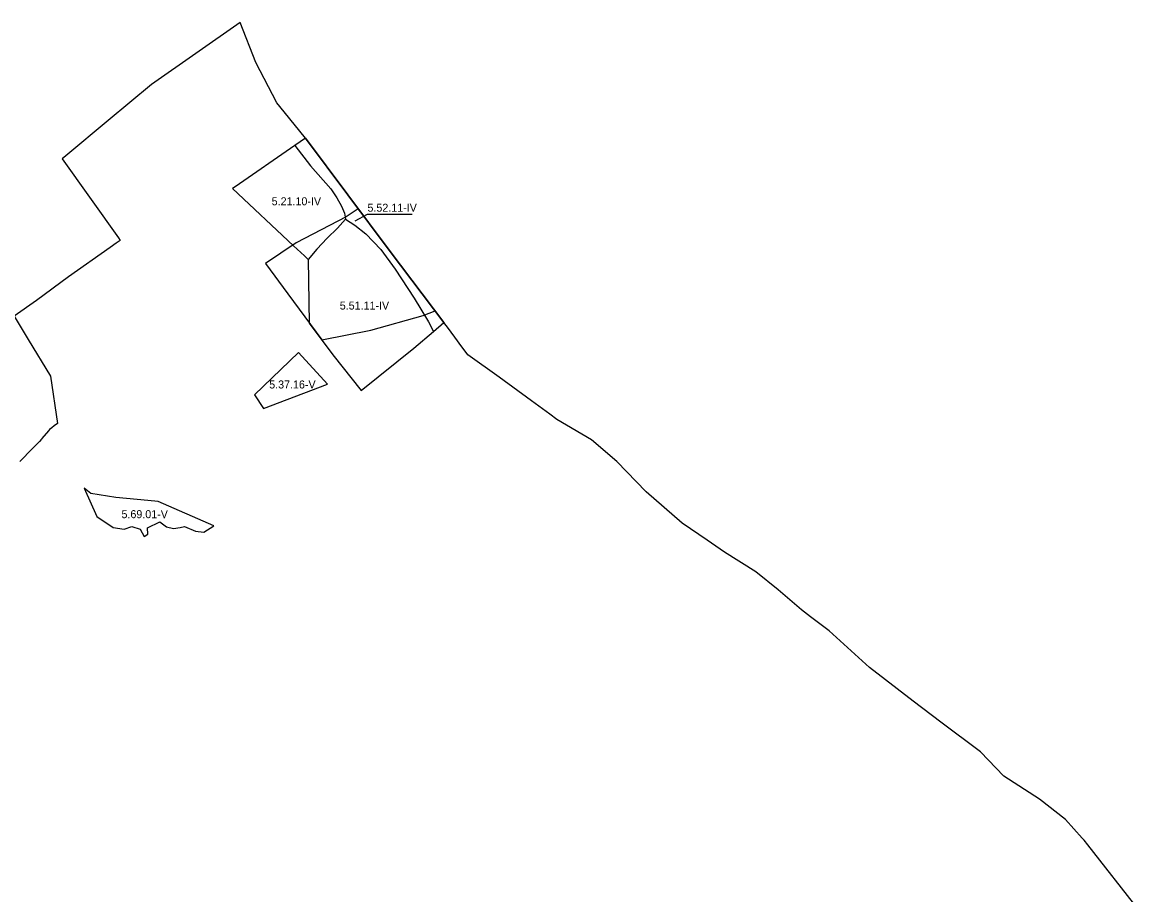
# Model space of a CAD drawing. Extents: x -555156 to -540209, y -1046851 to -1035695.
# Drawn here: x -543396 to -542000, y -1036785 to -1035695 of the extents above; entities that cross this region are included whole.
import ezdxf

# ---------------------------------------------------------------- set-up
doc = ezdxf.new("R2010")
doc.units = 0
for name, color, linetype in [('Vrstva 27', 7, 'Continuous'), ('Vrstva 28', 7, 'Continuous'), ('Vrstva 29', 7, 'Continuous')]:
    doc.layers.add(name, color=color, linetype=linetype)

msp = doc.modelspace()

# ---------------------------------------------------------------- linework, layer by layer
at = {"layer": 'Vrstva 27'}
msp.add_lwpolyline([(-542980.74, -1035942.52), (-542964.97, -1035934.43), (-542909.14, -1035934.43)], dxfattribs=at)
at = {"layer": 'Vrstva 28'}
for points in [[(-542936.69, -1035980.71), (-543042.64, -1035839.41), (-543069.25, -1035806.38), (-543078.47, -1035794.93), (-543104.67, -1035744.61), (-543124.3, -1035694.54), (-543234.87, -1035772.4), (-543289.16, -1035817.01), (-543341.94, -1035861.47), (-543346.51, -1035865.17), (-543276.38, -1035963.9), (-543274.21, -1035966.98), (-543279.27, -1035970.33), (-543286.85, -1035975.71), (-543338.82, -1036012.58), (-543378.67, -1036042.29), (-543406.66, -1036061.87), (-543389.24, -1036090.92), (-543361.26, -1036136.78), (-543352.67, -1036195.74), (-543356.78, -1036198.98), (-543359.45, -1036201.08), (-543362.4, -1036203.41), (-543363.78, -1036205.03), (-543372.06, -1036214.73), (-543372.5, -1036215.25), (-543374.91, -1036218.16), (-543375.33, -1036218.59), (-543383.53, -1036226.94), (-543399.68, -1036243.41)], [(-543056.03, -1035848.65), (-543130.42, -1035899.99), (-543133.72, -1035902.27), (-543057.58, -1035973.76), (-543043.99, -1035986.52), (-543039.28, -1035990.94)], [(-543042.64, -1035839.41), (-543056.03, -1035848.65)], [(-543056.03, -1035848.65), (-543036.31, -1035873.81), (-543011.09, -1035902.59), (-543003.25, -1035913.97), (-542997.68, -1035924.1), (-542993.89, -1035933.2), (-542992.63, -1035940.54)], [(-543042.64, -1035839.41), (-542936.69, -1035980.71), (-542869.66, -1036069.79)], [(-542992.63, -1035940.54), (-543002.49, -1035951.67), (-543015.39, -1035964.32), (-543028.53, -1035977.99), (-543039.28, -1035990.94)], [(-542992.63, -1035940.54), (-542981.06, -1035947.96), (-542967.15, -1035958.84), (-542948.44, -1035978.32), (-542930.48, -1036003.11), (-542906.97, -1036039.04), (-542888.76, -1036068.9), (-542882.84, -1036081.03)], [(-542000.32, -1036804.67), (-542065.05, -1036722.45), (-542069.84, -1036716.38), (-542072.11, -1036713.85), (-542092.81, -1036690.69), (-542125.62, -1036665.28), (-542169.9, -1036636.7), (-542199.3, -1036605.98), (-542248.78, -1036568.89), (-542283.5, -1036542.65), (-542337.95, -1036500.86), (-542388.29, -1036454.98), (-542411.43, -1036437.34), (-542422.75, -1036428.73), (-542451.96, -1036403.63), (-542480.03, -1036381.28), (-542519.01, -1036356.5), (-542540.89, -1036341.56), (-542571.93, -1036320.38), (-542617.03, -1036281.33), (-542653.65, -1036243.36), (-542685.07, -1036216.26), (-542728.49, -1036190.78), (-542737.26, -1036184.38), (-542760.08, -1036167.71), (-542800.8, -1036137.97), (-542839.61, -1036109.9), (-542850.49, -1036095.36), (-542852.5, -1036092.68), (-542864.03, -1036077.27), (-542869.66, -1036069.79), (-542936.69, -1035980.71)], [(-543039.28, -1035990.94), (-543037.82, -1036070.56)], [(-543037.82, -1036070.56), (-543008.45, -1036110.22), (-542973.1, -1036154.53), (-542907.11, -1036101.72), (-542882.84, -1036081.03)], [(-542882.84, -1036081.03), (-542869.66, -1036069.79)], [(-543015.14, -1036146.73), (-543051.27, -1036106.94), (-543106.33, -1036159.96)], [(-543106.33, -1036159.96), (-543094.92, -1036177.31), (-543015.14, -1036146.73)], [(-543226.53, -1036293.22), (-543239.72, -1036292.11), (-543279.75, -1036288.26), (-543310.74, -1036283.2), (-543319.36, -1036276.61), (-543303.31, -1036312.03), (-543282.87, -1036325.85)], [(-543282.87, -1036325.85), (-543269.18, -1036327.76), (-543259.8, -1036324.61), (-543249.14, -1036328.04), (-543244.31, -1036337.19), (-543239.76, -1036334.16), (-543239.82, -1036326.13), (-543224.67, -1036318.72), (-543216.36, -1036324.95), (-543207.38, -1036327.26), (-543199.07, -1036325.91), (-543193.86, -1036324.67), (-543180.16, -1036330.34), (-543169.44, -1036331.52), (-543157.26, -1036323.6), (-543226.53, -1036293.22)]]:
    msp.add_lwpolyline(points, dxfattribs=at)
at = {"layer": 'Vrstva 29'}
msp.add_lwpolyline([(-542976.613526, -1035927.466071), (-542991.700989, -1035937.507996), (-543054.310974, -1035970.11499), (-543092.395996, -1035995.908997), (-543064.487, -1036033.662903), (-543022.072998, -1036091.120972), (-542960.935974, -1036079.307007), (-542895.523987, -1036061.054993), (-542880.644288, -1036055.192351), (-542936.69, -1035980.71), (-542969.60783, -1035936.809204), (-542976.613526, -1035927.466071)], dxfattribs=at)

# ---------------------------------------------------------------- texts
at = {"layer": 'Vrstva 27'}
for s, p in [('5.21.10-IV', (-543084.86707, -1035923.15)), ('5.52.11-IV', (-542965.177241, -1035931.21)), ('5.51.11-IV', (-542999.787241, -1036053.47)), ('5.37.16-V', (-543087.947974, -1036152.09)), ('5.69.01-V', (-543272.531006, -1036314.17))]:
    msp.add_text(s, height=10, dxfattribs=at).set_placement(p)

doc.saveas('drawing.dxf')
